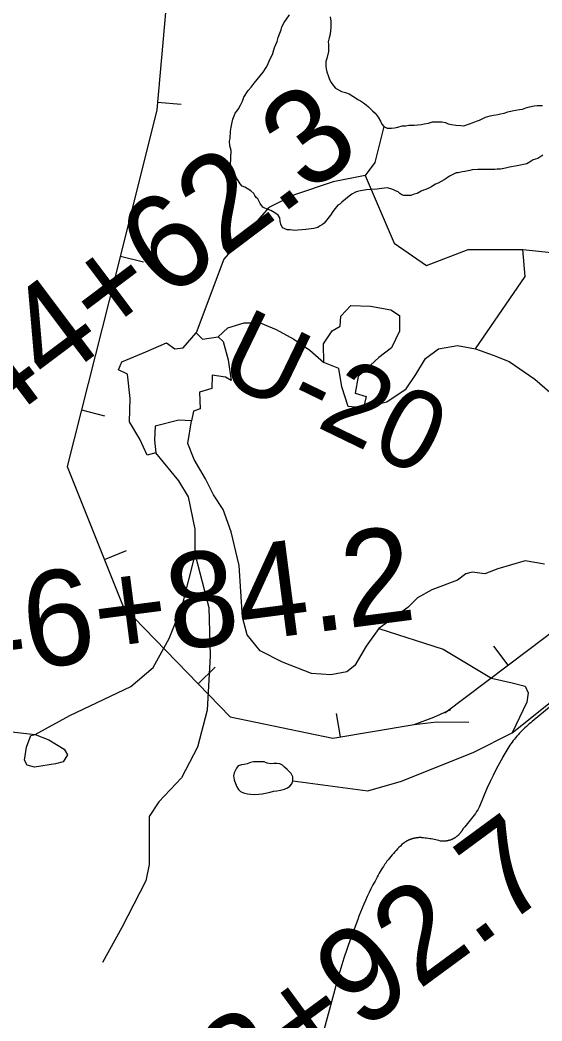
# Model space of a CAD drawing. Extents: x 3180038 to 3217926, y 922069 to 947485.
# Drawn here: x 3190489 to 3191038, y 942147 to 943199 of the extents above; entities that cross this region are included whole.
import ezdxf

# ---------------------------------------------------------------- set-up
doc = ezdxf.new("R2010")
doc.units = 0
for name, color, linetype in [('V-BORW-LINE', 7, 'Continuous'), ('V-RIVR-RANG-IDEN', 7, 'Continuous'), ('V-ROAD-CNTR', 7, 'Continuous'), ('V-SITE-VEGE', 7, 'Continuous'), ('V-SURV-IDEN', 7, 'Continuous'), ('V-TOPO-SHOR', 7, 'Continuous')]:
    doc.layers.add(name, color=color, linetype=linetype)

msp = doc.modelspace()

# ---------------------------------------------------------------- linework, layer by layer
at = {"layer": 'V-BORW-LINE'}
for p, q in [((3190634, 943112.6), (3190658.9, 943110.4)), ((3190595, 942950.8), (3190619.2, 942944.7)), ((3190554, 942789.3), (3190578.3, 942783.1)), ((3190578.1, 942632.1), (3190601.3, 942641.4)), ((3191002.6, 942521.1), (3190987.6, 942541.1)), ((3190676.8, 942501.4), (3190694.8, 942518.8)), ((3190826.4, 942445.7), (3190822.3, 942470.4))]:
    msp.add_line(p, q, dxfattribs=at)
for points in [[(3190650.6, 943297.7), (3190633.3, 943104.5)], [(3190633.3, 943104.5), (3190590.6, 942933.2)], [(3190590.6, 942933.2), (3190538.9, 942729.8)], [(3190538.9, 942729.8), (3190597.8, 942582.7)], [(3191024.3, 942537.4), (3191250.7, 942708.5)], [(3190597.8, 942582.7), (3190710.5, 942466.7)], [(3190936, 942471.1), (3191024.3, 942537.4)], [(3190710.5, 942466.7), (3190818.3, 942444.4)], [(3190904, 942458.5), (3190924.6, 942466.3)], [(3190924.6, 942466.3), (3190942.6, 942474.5)], [(3190818.3, 942444.4), (3190904, 942458.5)], [(3190904, 942458.5), (3190927.8, 942461.3)], [(3190927.8, 942461.3), (3190961.2, 942461)]]:
    msp.add_lwpolyline(points, dxfattribs=at)
at = {"layer": 'V-ROAD-CNTR'}
for points in [[(3191078.1, 942503.2), (3191028, 942461.7), (3191028, 942461.7), (3191026.5, 942460.5), (3191024.9, 942459.2), (3191023.4, 942457.9), (3191021.9, 942456.5), (3191020.4, 942455.1), (3191018.9, 942453.7), (3191017.5, 942452.3), (3191016, 942450.9), (3191014.7, 942449.4), (3191013.3, 942447.9), (3191012, 942446.4), (3191010.6, 942444.8), (3191009.4, 942443.3), (3191008.1, 942441.7), (3191006.9, 942440.1), (3191005.7, 942438.5), (3191004.5, 942436.8), (3191003.4, 942435.1), (3191002.3, 942433.4), (3191001.2, 942431.7), (3191000.1, 942430), (3190999.1, 942428.3), (3190998.1, 942426.5), (3190997.1, 942424.7), (3190997, 942424.4), (3190997, 942424.4), (3190993.5, 942418), (3190990.1, 942411.6), (3190986.8, 942405.1), (3190983.7, 942398.6), (3190980.6, 942392), (3190977.7, 942385.3), (3190974.9, 942378.6), (3190972.2, 942371.8), (3190971.9, 942371), (3190971.9, 942371), (3190970.7, 942369.1), (3190969.4, 942367.2), (3190968.2, 942365.3), (3190966.9, 942363.5), (3190965.6, 942361.7), (3190964.2, 942359.9), (3190962.8, 942358.1), (3190961.4, 942356.4), (3190960, 942354.6), (3190958.6, 942352.9), (3190957.1, 942351.3), (3190955.6, 942349.6), (3190955.3, 942349.3), (3190955.3, 942349.3), (3190955.1, 942348.9), (3190954.9, 942348.5), (3190954.7, 942348.1), (3190954.5, 942347.8), (3190954.3, 942347.4), (3190954, 942347.1), (3190953.8, 942346.7), (3190953.6, 942346.4), (3190953.4, 942346), (3190953.1, 942345.7), (3190952.9, 942345.4), (3190952.6, 942345), (3190952.4, 942344.7), (3190952.1, 942344.4), (3190951.8, 942344.1), (3190951.5, 942343.7), (3190951.3, 942343.4), (3190951, 942343.1), (3190950.7, 942342.8), (3190950.4, 942342.5), (3190950.1, 942342.2)], [(3190950.1, 942342.2), (3190949.8, 942342), (3190949.5, 942341.7), (3190949.1, 942341.4), (3190948.8, 942341.1), (3190948.5, 942340.9), (3190948.2, 942340.6), (3190947.8, 942340.4), (3190947.5, 942340.1), (3190947.2, 942339.9), (3190946.8, 942339.6), (3190946.5, 942339.4), (3190946.1, 942339.2), (3190945.7, 942339), (3190945.4, 942338.8), (3190945, 942338.6), (3190944.6, 942338.4), (3190944.3, 942338.2), (3190944.1, 942338.1), (3190944.1, 942338.1), (3190943.7, 942337.9), (3190943.3, 942337.8), (3190943, 942337.6), (3190942.6, 942337.5), (3190942.2, 942337.3), (3190941.9, 942337.2), (3190941.5, 942337.1), (3190941.1, 942337), (3190940.7, 942336.9), (3190940.3, 942336.8), (3190939.9, 942336.7), (3190939.6, 942336.6), (3190939.2, 942336.5), (3190938.8, 942336.4), (3190938.4, 942336.3), (3190938, 942336.3), (3190937.6, 942336.2), (3190937.2, 942336.2), (3190936.8, 942336.1), (3190936.4, 942336.1), (3190936, 942336.1), (3190935.6, 942336), (3190935.2, 942336), (3190934.8, 942336), (3190934.4, 942336), (3190934, 942336), (3190933.7, 942336), (3190933.3, 942336), (3190932.9, 942336.1), (3190932.5, 942336.1), (3190932.1, 942336.1), (3190931.7, 942336.2), (3190931.4, 942336.2), (3190931.4, 942336.2), (3190929.8, 942336.6), (3190928.2, 942337.1), (3190926.6, 942337.4), (3190925, 942337.8), (3190923.4, 942338.1), (3190921.8, 942338.5), (3190920.2, 942338.7), (3190918.6, 942339), (3190917, 942339.2), (3190915.4, 942339.4), (3190913.8, 942339.6), (3190912.1, 942339.7), (3190912.1, 942339.7), (3190912.1, 942339.7), (3190911.6, 942339.8), (3190911, 942339.8), (3190910.5, 942339.8), (3190910, 942339.8), (3190909.5, 942339.8), (3190909, 942339.8), (3190908.5, 942339.8), (3190908, 942339.7), (3190907.5, 942339.7), (3190907, 942339.6), (3190906.5, 942339.6), (3190906, 942339.5), (3190905.5, 942339.4), (3190905, 942339.3), (3190904.5, 942339.2), (3190904, 942339.1), (3190903.5, 942339), (3190903, 942338.9), (3190902.5, 942338.8), (3190902, 942338.6), (3190901.5, 942338.5), (3190901, 942338.3), (3190900.5, 942338.1), (3190900.1, 942338), (3190899.6, 942337.8), (3190899.1, 942337.6), (3190898.6, 942337.4), (3190898.2, 942337.2), (3190897.7, 942337), (3190897.2, 942336.8), (3190896.8, 942336.5), (3190896.3, 942336.3), (3190895.9, 942336)], [(3190895.9, 942336), (3190895.5, 942335.8), (3190895, 942335.5), (3190894.6, 942335.3), (3190894.2, 942335), (3190893.7, 942334.7), (3190893.3, 942334.4), (3190892.9, 942334.1), (3190892.5, 942333.8), (3190892.5, 942333.8), (3190890.9, 942332.4), (3190889.4, 942330.9), (3190887.8, 942329.4), (3190886.3, 942327.9), (3190884.8, 942326.4), (3190883.4, 942324.8), (3190882, 942323.2), (3190880.6, 942321.6), (3190879.2, 942319.9), (3190877.8, 942318.3), (3190876.5, 942316.6), (3190875.3, 942314.9), (3190874, 942313.1), (3190872.8, 942311.4), (3190871.6, 942309.6), (3190870.4, 942307.8), (3190869.3, 942306), (3190868.2, 942304.1), (3190867.1, 942302.3), (3190866.1, 942300.4), (3190865.1, 942298.5), (3190864.9, 942298.1), (3190864.9, 942298.1), (3190862.7, 942294.1), (3190860.5, 942290.2), (3190858.4, 942286.1), (3190856.4, 942282.1), (3190854.5, 942278), (3190852.6, 942273.9), (3190850.8, 942269.7), (3190849.1, 942265.5), (3190847.4, 942261.3), (3190845.8, 942257.1), (3190844.7, 942253.9), (3190844.7, 942253.9), (3190840.8, 942243.7), (3190837, 942233.5), (3190833.4, 942223.3), (3190830, 942213), (3190826.8, 942202.6), (3190823.7, 942192.2), (3190822.5, 942188), (3190822.5, 942188), (3190803.4, 942116.8)]]:
    msp.add_lwpolyline(points, dxfattribs=at)
at = {"layer": 'V-SITE-VEGE'}
for points in [[(3190721, 943026.9), (3190711.1, 943042.9), (3190710.6, 943046.1), (3190711.3, 943061.9), (3190710.2, 943066.7), (3190709.7, 943071.5), (3190710.3, 943074.6), (3190710.9, 943082), (3190711.4, 943086.3), (3190712, 943090), (3190713.1, 943094.7), (3190714.7, 943098.4), (3190715.8, 943101.1), (3190717.4, 943103.2), (3190719, 943105.8), (3190721.1, 943109.5), (3190723.3, 943113.7), (3190724.9, 943117.9), (3190729.2, 943124.8), (3190732.4, 943128.4), (3190735.6, 943132.6), (3190745.2, 943144.2), (3190748.4, 943148.9), (3190749.5, 943151.6), (3190752.2, 943157.4), (3190754.9, 943162.6), (3190757.1, 943170), (3190759.8, 943176.4), (3190760.8, 943180.6), (3190762.5, 943185.3), (3190764.1, 943188.5), (3190764.6, 943191.7), (3190767.3, 943196.4), (3190772.7, 943204.3)], [(3191039.2, 943056.8), (3191033.9, 943053.6), (3191029.1, 943052.1), (3191027, 943050.5), (3191022.2, 943047.9), (3191012.1, 943045.9), (3191004.2, 943044.3), (3191000, 943043.3), (3190994.7, 943042.3), (3190991, 943042.3), (3190988.8, 943041.8), (3190979.8, 943041.9), (3190974, 943041.9), (3190970.9, 943041.9), (3190965, 943041.5), (3190962.4, 943040.9), (3190957.1, 943039.9), (3190954.4, 943039.4), (3190950.2, 943038.4), (3190948.1, 943038.4), (3190946, 943037.4), (3190941.2, 943034.8), (3190938.5, 943033.2), (3190935.3, 943031.1), (3190929, 943027.5), (3190926.3, 943026.4), (3190923.6, 943024.8), (3190921.5, 943023.3), (3190916.2, 943020.7), (3190913.6, 943020.2), (3190911.4, 943019.1), (3190907.2, 943016.5), (3190904, 943016), (3190900.3, 943014.5), (3190898.2, 943014.5), (3190895, 943014.5), (3190892.9, 943014.5), (3190890.8, 943015.1), (3190888.7, 943016.7), (3190887.1, 943018.3), (3190884.4, 943019.3), (3190881.3, 943020.9), (3190879.2, 943021.5), (3190875.5, 943022.6), (3190872.8, 943022.1), (3190867, 943021.6), (3190864.9, 943021.1), (3190853.8, 943020.6), (3190847.4, 943019.6), (3190844.2, 943018.6), (3190842.1, 943018.1), (3190838.4, 943016), (3190835.7, 943013.9), (3190827.8, 943007.6), (3190825.6, 943005.5), (3190823.5, 943004.5), (3190820.8, 943000.8), (3190818.2, 942997.6), (3190816, 942993.9), (3190809.1, 942985.5), (3190807.5, 942984), (3190804.3, 942982.4), (3190802.7, 942980.8), (3190798.4, 942979.8), (3190790, 942978.8), (3190781.5, 942978.3), (3190778.3, 942977.8), (3190773.6, 942978.4), (3190770.4, 942978.4), (3190765.6, 942980.6), (3190763.6, 942984.3), (3190763.1, 942987.5), (3190762.6, 942991.2), (3190761, 942993.8), (3190757.3, 942996.5), (3190753.1, 942998.7), (3190750.5, 942999.7), (3190746.8, 943001.4), (3190744.7, 943002.4), (3190742, 943006.2), (3190739.4, 943010.9), (3190737.9, 943012.5), (3190736.3, 943014.7), (3190735.2, 943016.8), (3190732.1, 943019.5), (3190729.5, 943021.1), (3190725.8, 943023.2), (3190723.1, 943024.3), (3190721, 943026.9)]]:
    msp.add_lwpolyline(points, dxfattribs=at)
at = {"layer": 'V-TOPO-SHOR'}
for points in [[(3190776.2, 942399.4), (3190855, 942389.1), (3190890.5, 942399.2), (3190966.5, 942429.6), (3191007, 942449.9), (3191309.4, 942691.4), (3191528.9, 942857), (3191559.3, 942895.8), (3191586.4, 942953.2), (3191655.6, 943096.8), (3191863.3, 943517.3), (3191998.5, 943787.6), (3191993.4, 943801.1), (3191986.6, 943804.5), (3191974.8, 943809.7)], [(3190815.6, 943202.3), (3190816.1, 943197.8), (3190816.4, 943194.2), (3190816.2, 943191.2), (3190815.8, 943188), (3190815.6, 943184.2), (3190814.5, 943180.3), (3190813.6, 943176.2), (3190813.9, 943173.1), (3190813.9, 943169.2), (3190813.8, 943166), (3190812, 943158.6), (3190811.1, 943155.3), (3190810.9, 943150.6), (3190811.4, 943147.6), (3190812.1, 943144.5), (3190813.8, 943139.5), (3190815, 943136.3), (3190816.6, 943133.2), (3190819.1, 943129.8), (3190821.1, 943127.5), (3190824.4, 943125.5), (3190827.3, 943123.8), (3190831.6, 943122.7), (3190835.7, 943121.4), (3190839.4, 943119.1), (3190842.1, 943117.1), (3190844.8, 943115.3), (3190847.6, 943114), (3190850.6, 943112), (3190853.3, 943109.7), (3190855.8, 943107.7), (3190858.1, 943105.7), (3190860.2, 943103.5), (3190862.7, 943101.2), (3190865.9, 943096.9), (3190868.6, 943092.6), (3190870, 943089.5), (3190871.9, 943087.2), (3190875.5, 943085.3), (3190880.1, 943085.3), (3190883.2, 943085.8), (3190886.6, 943086.5), (3190891.4, 943087.6), (3190895.2, 943087.7), (3190898.4, 943088.4), (3190898.6, 943088.6), (3190903.8, 943088.5), (3190907.7, 943088.9), (3190911.1, 943089.2), (3190914.3, 943089.9), (3190918.8, 943090.7), (3190923.1, 943091.8), (3190926.3, 943092.1), (3190929.7, 943092.1), (3190933, 943092.1), (3190936.7, 943091.1), (3190939.7, 943089.9), (3190943.1, 943089.3), (3190947.8, 943088.5), (3190953.1, 943088), (3190956.2, 943087.9), (3190962.1, 943089.9), (3190966, 943091.1)], [(3190966, 943091.1), (3190969.6, 943092.5), (3190972.5, 943093.7), (3190976.1, 943095.5), (3190979, 943096.7), (3190983.8, 943098.1), (3190987.4, 943098.8), (3190991.7, 943099.7), (3190994.7, 943100.2), (3190998.5, 943100.9), (3191002.3, 943102.4), (3191006.9, 943103.7), (3191010.9, 943104.3), (3191014.8, 943105), (3191017.8, 943105.4), (3191021.4, 943106.6), (3191025, 943107.8), (3191029.9, 943108.7), (3191033.3, 943109.2), (3191037.2, 943109.1), (3191038.8, 943109.1)], [(3190871.9, 943087.2), (3190862.6, 943049.1), (3190852.5, 943035.6), (3190818.7, 943028.8), (3190778.2, 943015.3), (3190751.2, 943001.8), (3190703.9, 942947.7), (3190674.7, 942870.1)], [(3190852.5, 943035.6), (3190882.9, 942964.6), (3190916.7, 942941), (3190960.6, 942957.9), (3191018, 942957.9), (3191048.4, 942954.5), (3191072.1, 942944.4), (3191092.3, 942947.7), (3191102.5, 942954.5), (3191146.4, 942974.8), (3191163.3, 942927.5), (3191186.9, 942873.4), (3191203.8, 942792.4), (3191209, 942756.8)], [(3190968.2, 942853.6), (3191020.5, 942929.6), (3191018, 942957.9)], [(3190879.2, 942894.4), (3190888.3, 942888.5), (3190888.6, 942872.1), (3190880.2, 942854.4), (3190866.6, 942844.3), (3190853.5, 942832), (3190844.9, 942824.5), (3190841.8, 942806.9), (3190853.3, 942803.2), (3190850.5, 942791.3), (3190834.5, 942792.9), (3190827.8, 942813.6), (3190824.6, 942832.9), (3190809, 942839.2), (3190808.6, 942858.8), (3190817.5, 942872.5), (3190826, 942877.4), (3190826.8, 942887.8), (3190837.4, 942898.8), (3190858, 942898.2), (3190879.2, 942894.4)], [(3190697.8, 942866), (3190708.1, 942875.5), (3190725, 942880.6), (3190741.9, 942880.6), (3190758.8, 942873.8), (3190777.3, 942863.7), (3190794.2, 942851.9), (3190809, 942839.2)], [(3190661, 942854.4), (3190674.7, 942870.1), (3190681.2, 942863.7), (3190697.8, 942866), (3190703.2, 942861.3), (3190708.4, 942841.9), (3190711.5, 942820.1), (3190705.6, 942823.5), (3190691.6, 942825.6), (3190691.1, 942811.7), (3190678.2, 942807.9), (3190678.9, 942790.5), (3190671.7, 942787.9), (3190669.9, 942777.7), (3190656.5, 942778.5), (3190631.6, 942772.3), (3190631, 942757.5), (3190632.3, 942744.2), (3190623.2, 942741.7), (3190615.3, 942758.4), (3190604.4, 942776.6), (3190605.3, 942801.4), (3190602.5, 942826.7), (3190593, 942831.2), (3190596.6, 942839.9), (3190621.8, 942850.2), (3190643.3, 942859.7), (3190652.3, 942853.4), (3190661, 942854.4)], [(3190850.5, 942791.3), (3190875.3, 942797.8), (3190895.6, 942811.4), (3190905.7, 942826.6), (3190915.8, 942843.4), (3190929.3, 942853.6), (3190949.6, 942857), (3190968.2, 942853.6), (3190986.8, 942846.8), (3191003.7, 942840.1), (3191030.7, 942821.5), (3191054.3, 942801.2), (3191071.2, 942779.3), (3191101.6, 942753.9), (3191132, 942732), (3191143.8, 942725.2), (3191166.2, 942711.6)], [(3191040.8, 942627.3), (3191020.5, 942630.6), (3190991.8, 942622.2), (3190978.3, 942617.1), (3190964.8, 942618.8), (3190958.1, 942617.1), (3190949.6, 942610.4), (3190922.6, 942600.2), (3190907.4, 942591.8), (3190897.3, 942581.7), (3190866.8, 942559.7), (3190853.3, 942541.1), (3190841.5, 942520.8), (3190833.1, 942514.1), (3190816.2, 942510.7), (3190795.9, 942512.4), (3190765.5, 942524.2), (3190741.9, 942536), (3190728.4, 942552.9), (3190723.3, 942571.5), (3190721.6, 942598.5), (3190719.9, 942625.6), (3190711.5, 942661), (3190703, 942684.7), (3190692.9, 942699.9), (3190684.4, 942716.8), (3190672.6, 942737), (3190665.9, 942753.9), (3190669.9, 942777.7)], [(3190343.6, 942414.8), (3190396.5, 942417.4), (3190450.5, 942437.7), (3190477.5, 942451.2), (3190505.5, 942448.1), (3190541.7, 942468.1), (3190605.9, 942498.5), (3190629.5, 942518.7), (3190646.4, 942549.1), (3190659.9, 942582.9), (3190673.5, 942637), (3190673.5, 942664), (3190666.7, 942697.8), (3190656.6, 942714.7), (3190632.3, 942744.2)], [(3190673.5, 942637), (3190687.8, 942581.7), (3190689.5, 942531), (3190686.1, 942473.6), (3190676, 942434.7), (3190659.1, 942402.6), (3190635.5, 942377.3), (3190625.3, 942362.1), (3190625.3, 942355.3), (3190625.3, 942338.4), (3190625.3, 942311.4), (3190621.9, 942294.5), (3190596.6, 942245.5), (3190576.3, 942208.4)], [(3190866.8, 942559.7), (3190934.4, 942537.7), (3190985.1, 942507.3), (3191007, 942502.3), (3191020.5, 942498.9), (3191023.9, 942492.1), (3191022.2, 942482), (3191007, 942449.9)], [(3190504.7, 942414), (3190497, 942416), (3190494.1, 942421.1), (3190496.4, 942434.9), (3190500.7, 942447.2), (3190505.5, 942448.1), (3190519.8, 942442.6), (3190535.8, 942432.6), (3190539.4, 942426.7), (3190534.9, 942419.6), (3190526.6, 942417.3), (3190504.7, 942414)], [(3190714.6, 942407.9), (3190714, 942404.7), (3190714.7, 942400.6), (3190715.9, 942396.6), (3190717.3, 942393.2), (3190719.1, 942390.5), (3190721.4, 942388.2), (3190724.6, 942386.7), (3190728.6, 942385.8), (3190731.8, 942385.6), (3190735.9, 942385), (3190740.4, 942385.3), (3190743.9, 942385.8), (3190747.7, 942386.5), (3190752.4, 942387.7), (3190755.8, 942388.6), (3190759.4, 942389.1), (3190763.3, 942389.5), (3190767.6, 942390.7), (3190770.6, 942392.1), (3190773.3, 942393.8), (3190775.2, 942396.3), (3190776.2, 942399.4), (3190776.3, 942403.7), (3190774.7, 942407.1), (3190772.6, 942409.2), (3190770.4, 942411.4), (3190767.6, 942413.7), (3190765.5, 942415.9), (3190762.8, 942417.4), (3190759.6, 942417.7), (3190756.4, 942417.6), (3190753.3, 942417.4), (3190749.4, 942418.2), (3190746.2, 942419.3), (3190743.1, 942419.5), (3190739.4, 942419.5), (3190735.1, 942419.4), (3190731.7, 942418.7), (3190728.4, 942417.4), (3190725.2, 942416.6), (3190722.2, 942416.4), (3190718.9, 942415.2), (3190717, 942412.9), (3190714.6, 942407.9)]]:
    msp.add_lwpolyline(points, dxfattribs=at)

# ---------------------------------------------------------------- texts
at = {"layer": 'V-RIVR-RANG-IDEN'}
msp.add_text('U-20', height=83, rotation=334.1632, dxfattribs=at).set_placement((3190694.3, 942823.2))
at = {"layer": 'V-SURV-IDEN'}
for s, rotation, p in [('244+62.3', 36.9464, (3190402.8, 942722.3)), ('246+84.2', 7.3739, (3190351.2, 942497.4)), ('253+92.7', 36.3105, (3190605.7, 941956.7)), ('259+01.4', 64.4211, (3191080.4, 941743.3))]:
    msp.add_text(s, height=100, rotation=rotation, dxfattribs=at).set_placement(p)

doc.saveas('drawing.dxf')
